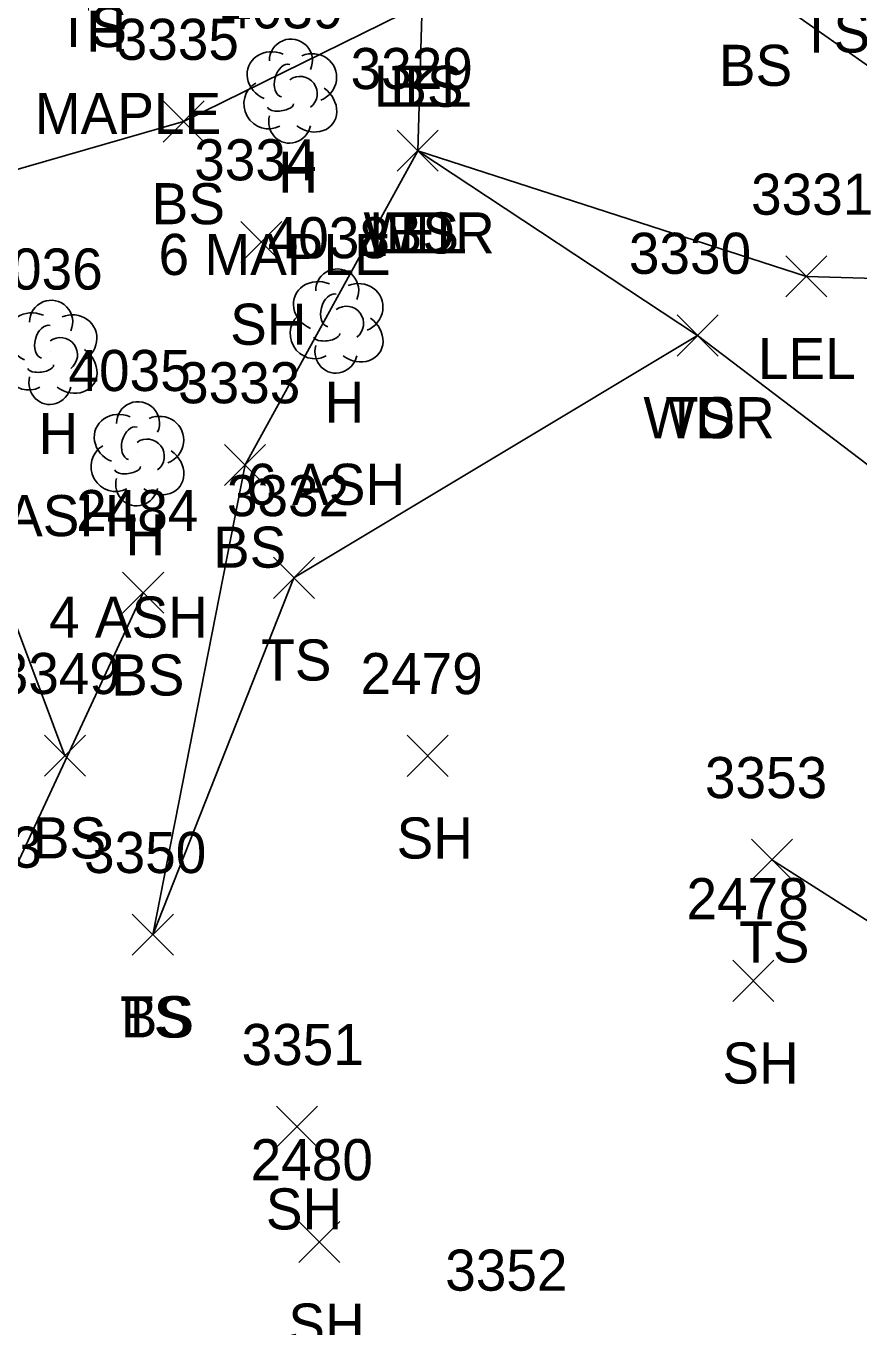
# Model space of a CAD drawing. Extents: x 1461855 to 1464118, y 556196 to 557441.
# Drawn here: x 1462017.7 to 1462058.2, y 556555.9 to 556619.2 of the extents above; entities that cross this region are included whole.
import ezdxf

# ---------------------------------------------------------------- set-up
doc = ezdxf.new("R2010")
doc.units = 0
for name, color, linetype in [('L_A', 7, 'Continuous'), ('L_C', 7, 'Continuous'), ('L_I', 7, 'Continuous'), ('L_TIC', 7, 'Continuous'), ('LARO', 7, 'Continuous'), ('LAWA', 7, 'Continuous'), ('LELB', 7, 'Continuous'), ('LTD', 7, 'Continuous')]:
    doc.layers.add(name, color=color, linetype=linetype)

msp = doc.modelspace()

# ---------------------------------------------------------------- linework, layer by layer
at = {"layer": 'L_TIC'}
for points in [[(1462024.387, 556613.515), (1462026.387, 556615.515)], [(1462026.387, 556613.515), (1462024.387, 556615.515)], [(1462035.776, 556612.093), (1462037.776, 556614.093)], [(1462037.776, 556612.093), (1462035.776, 556614.093)], [(1462035.776, 556612.093), (1462037.776, 556614.093)], [(1462037.776, 556612.093), (1462035.776, 556614.093)], [(1462035.776, 556612.093), (1462037.776, 556614.093)], [(1462037.776, 556612.093), (1462035.776, 556614.093)], [(1462028.161, 556607.651), (1462030.161, 556609.651)], [(1462030.161, 556607.651), (1462028.161, 556609.651)], [(1462054.688, 556605.979), (1462056.688, 556607.979)], [(1462056.688, 556605.979), (1462054.688, 556607.979)], [(1462049.396, 556603.102), (1462051.396, 556605.102)], [(1462051.396, 556603.102), (1462049.396, 556605.102)], [(1462049.396, 556603.102), (1462051.396, 556605.102)], [(1462051.396, 556603.102), (1462049.396, 556605.102)], [(1462027.375, 556596.803), (1462029.375, 556598.803)], [(1462029.375, 556596.803), (1462027.375, 556598.803)], [(1462029.751, 556591.31), (1462031.751, 556593.31)], [(1462031.751, 556591.31), (1462029.751, 556593.31)], [(1462022.416, 556590.583), (1462024.416, 556592.583)], [(1462024.416, 556590.583), (1462022.416, 556592.583)], [(1462018.608, 556582.655), (1462020.608, 556584.655)], [(1462020.608, 556582.655), (1462018.608, 556584.655)], [(1462036.259, 556582.649), (1462038.259, 556584.649)], [(1462038.259, 556582.649), (1462036.259, 556584.649)], [(1462053.01, 556577.59), (1462055.01, 556579.59)], [(1462055.01, 556577.59), (1462053.01, 556579.59)], [(1462022.886, 556573.944), (1462024.886, 556575.944)], [(1462024.886, 556573.944), (1462022.886, 556575.944)], [(1462022.886, 556573.944), (1462024.886, 556575.944)], [(1462024.886, 556573.944), (1462022.886, 556575.944)], [(1462052.11, 556571.698), (1462054.11, 556573.698)], [(1462054.11, 556571.698), (1462052.11, 556573.698)], [(1462029.898, 556564.6), (1462031.898, 556566.6)], [(1462031.898, 556564.6), (1462029.898, 556566.6)], [(1462030.993, 556558.995), (1462032.993, 556560.995)], [(1462032.993, 556558.995), (1462030.993, 556560.995)]]:
    msp.add_lwpolyline(points, dxfattribs=at)
at = {"layer": 'LARO'}
msp.add_lwpolyline([(1462028.293, 556804.845), (1462029.856, 556786.264), (1462034.967, 556768.458), (1462036.472, 556762.979), (1462033.427, 556748.898), (1462029.252, 556744.558), (1462032.364, 556727.057), (1462032.403, 556719.386), (1462031.75, 556687.131), (1462035.594, 556661.411), (1462033.996, 556641.147), (1462031.483, 556628.768), (1462037, 556620.231), (1462036.776, 556613.093), (1462055.688, 556606.979), (1462067.548, 556606.631), (1462078.525, 556595.396), (1462093.66, 556580.158), (1462100.331, 556564.645), (1462103.465, 556550.963), (1462104.582, 556534.352), (1462113.504, 556526.22)], dxfattribs=at)
at = {"layer": 'LAWA'}
msp.add_lwpolyline([(1462036.776, 556613.093), (1462050.396, 556604.102), (1462080.299, 556581.377), (1462088.118, 556572.25), (1462090.708, 556561.628), (1462095.286, 556550.274), (1462094.272, 556539.371)], dxfattribs=at)
at = {"layer": 'LELB'}
for points in [[(1462033.427, 556748.898), (1462037.255, 556728.002), (1462037.528, 556719.234), (1462036.024, 556686.385), (1462043.522, 556661.49), (1462038.833, 556639.233), (1462052.988, 556621.249), (1462067.983, 556610.68)], [(1462037, 556620.231), (1462025.387, 556614.515), (1462007.069, 556609.236), (1462003.91, 556604.783)], [(1462036.776, 556613.093), (1462028.375, 556597.803), (1462023.886, 556574.944)], [(1462007.069, 556609.236), (1462009.837, 556605.016), (1462011.898, 556601.66), (1462015.028, 556595.847), (1462019.608, 556583.655)], [(1462050.396, 556604.102), (1462030.751, 556592.31), (1462023.886, 556574.944)], [(1462073.826, 556488.172), (1462058.724, 556498.395), (1462047.72, 556513.704), (1462037.062, 556530.069), (1462022.313, 556535.546), (1462008.95, 556552.393), (1462011.129, 556562.18), (1462015.8, 556575.203), (1462023.416, 556591.583)], [(1462054.01, 556578.59), (1462066.074, 556570.901), (1462081.079, 556559.746), (1462094.272, 556539.371)]]:
    msp.add_lwpolyline(points, dxfattribs=at)
at = {"layer": 'LTD'}
for p, q in [((1462030.559, 556616.047), (1462030.559, 556616.047)), ((1462030.559, 556616.047), (1462030.559, 556616.047)), ((1462032.812, 556604.861), (1462032.812, 556604.861)), ((1462032.812, 556604.861), (1462032.812, 556604.861)), ((1462018.894, 556603.336), (1462018.894, 556603.336)), ((1462018.894, 556603.336), (1462018.894, 556603.336)), ((1462023.119, 556598.399), (1462023.119, 556598.399)), ((1462023.119, 556598.399), (1462023.119, 556598.399))]:
    msp.add_line(p, q, dxfattribs=at)
for centre in [(1462030.606, 556617.481), (1462032.859, 556606.295), (1462018.941, 556604.77), (1462023.166, 556599.833)]:
    msp.add_arc(centre, 1.047, 335.52715, 180.95627, dxfattribs=at)
for centre, major_axis, ratio, start_param, end_param in [((1462029.767, 556616.713), (1.21, -0.512), 0.895232, 1.570796, 4.712389), ((1462031.6, 556616.63), (-1.141, -0.483), 0.949671, 1.570796, 4.712389), ((1462030.35, 556616.505), (-0.208, -0.792), 0.645439, 3.141593, 6.283185), ((1462031.059, 556615.88), (-0.5, 0.667), 0.989748, 3.141593, 6.283185), ((1462029.476, 556615.338), (0.584, -1.042), 0.959034, 3.141593, 6.283185), ((1462031.559, 556615.214), (-1.09, 0.792), 0.841452, 1.570796, 4.712389), ((1462030.101, 556615.297), (-0.625, -0.083), 0.423636, 0, 3.141593), ((1462030.559, 556614.547), (0.265, 1.061), 0.942809, 1.570796, 4.712389), ((1462032.02, 556605.527), (1.21, -0.512), 0.895232, 1.570796, 4.712389), ((1462033.854, 556605.444), (-1.141, -0.483), 0.949671, 1.570796, 4.712389), ((1462032.604, 556605.319), (-0.208, -0.792), 0.645439, 3.141593, 6.283185), ((1462033.312, 556604.694), (-0.5, 0.667), 0.989748, 3.141593, 6.283185), ((1462018.102, 556604.003), (1.21, -0.512), 0.895232, 1.570796, 4.712389), ((1462019.936, 556603.92), (-1.141, -0.483), 0.949671, 1.570796, 4.712389), ((1462031.729, 556604.152), (0.584, -1.042), 0.959034, 3.141593, 6.283185), ((1462033.812, 556604.028), (-1.09, 0.792), 0.841452, 1.570796, 4.712389), ((1462018.686, 556603.795), (-0.208, -0.792), 0.645439, 3.141593, 6.283185), ((1462032.354, 556604.111), (-0.625, -0.083), 0.423636, 0, 3.141593), ((1462017.811, 556602.628), (0.584, -1.042), 0.959034, 3.141593, 6.283185), ((1462019.394, 556603.17), (-0.5, 0.667), 0.989748, 3.141593, 6.283185), ((1462032.812, 556603.361), (0.265, 1.061), 0.942809, 1.570796, 4.712389), ((1462019.894, 556602.503), (-1.09, 0.792), 0.841452, 1.570796, 4.712389), ((1462018.436, 556602.586), (-0.625, -0.083), 0.423636, 0, 3.141593), ((1462018.894, 556601.836), (0.265, 1.061), 0.942809, 1.570796, 4.712389), ((1462022.328, 556599.065), (1.21, -0.512), 0.895232, 1.570796, 4.712389), ((1462024.161, 556598.982), (-1.141, -0.483), 0.949671, 1.570796, 4.712389), ((1462022.911, 556598.857), (-0.208, -0.792), 0.645439, 3.141593, 6.283185), ((1462023.619, 556598.232), (-0.5, 0.667), 0.989748, 3.141593, 6.283185), ((1462022.036, 556597.69), (0.584, -1.042), 0.959034, 3.141593, 6.283185), ((1462024.12, 556597.565), (-1.09, 0.792), 0.841452, 1.570796, 4.712389), ((1462022.661, 556597.649), (-0.625, -0.083), 0.423636, 0, 3.141593), ((1462023.12, 556596.899), (0.265, 1.061), 0.942809, 1.570796, 4.712389)]:
    msp.add_ellipse(centre, major_axis=major_axis, ratio=ratio, start_param=start_param, end_param=end_param, dxfattribs=at)

# ---------------------------------------------------------------- texts
at = {"layer": 'L_A'}
for s, p in [('TS', (1462019.213, 556618.137)), ('H', (1462020.65, 556617.908)), ('TS', (1462055.366, 556617.87)), ('BS', (1462051.429, 556616.249)), ('LEL', (1462034.637, 556615.231)), ('BS', (1462035.441, 556615.231)), ('H', (1462029.992, 556611.047)), ('BS', (1462023.828, 556609.515)), ('WDR', (1462034.138, 556608.093)), ('LEL', (1462034.414, 556608.093)), ('BS', (1462035.217, 556608.093)), ('SH', (1462027.649, 556603.651)), ('LEL', (1462053.326, 556601.979)), ('H', (1462032.245, 556599.861)), ('WDR', (1462047.758, 556599.102)), ('TS', (1462048.805, 556599.102)), ('H', (1462018.327, 556598.336)), ('H', (1462022.552, 556593.399)), ('BS', (1462026.815, 556592.803)), ('TS', (1462029.161, 556587.31)), ('BS', (1462021.857, 556586.583)), ('BS', (1462018.049, 556578.655)), ('SH', (1462035.747, 556578.649)), ('TS', (1462052.419, 556573.59)), ('TS', (1462022.296, 556569.944)), ('BS', (1462022.327, 556569.944)), ('SH', (1462051.599, 556567.698)), ('SH', (1462029.386, 556560.6)), ('SH', (1462030.481, 556554.995))]:
    msp.add_text(s, height=2, dxfattribs=at).set_placement(p)
at = {"layer": 'L_C'}
for s, p in [('10 MAPLE', (1462014.429, 556613.908)), ('6 MAPLE', (1462024.165, 556607.047)), ('6 ASH', (1462028.434, 556595.861)), ('6 ASH', (1462014.516, 556594.336)), ('4 ASH', (1462018.836, 556589.399))]:
    msp.add_text(s, height=2, dxfattribs=at).set_placement(p)
at = {"layer": 'L_I'}
for s, p in [('4039', (1462027.212, 556619.047)), ('3335', (1462022.127, 556617.515)), ('3329', (1462033.509, 556616.093)), ('3329', (1462033.509, 556616.093)), ('3329', (1462033.509, 556616.093)), ('3334', (1462025.901, 556611.651)), ('3331', (1462052.995, 556609.979)), ('4038', (1462029.474, 556607.861)), ('3330', (1462047.049, 556607.102)), ('3330', (1462047.049, 556607.102)), ('4036', (1462015.501, 556606.336)), ('4035', (1462019.781, 556601.399)), ('3333', (1462025.115, 556600.803)), ('3332', (1462027.491, 556595.31)), ('2484', (1462020.156, 556594.583)), ('3349', (1462016.34, 556586.655)), ('2479', (1462033.991, 556586.649)), ('3353', (1462050.75, 556581.59)), ('2483', (1462012.54, 556578.203)), ('3350', (1462020.54, 556577.944)), ('3350', (1462020.54, 556577.944)), ('2478', (1462049.851, 556575.698)), ('3351', (1462028.205, 556568.6)), ('2480', (1462028.646, 556562.995)), ('3352', (1462038.113, 556557.62))]:
    msp.add_text(s, height=2, dxfattribs=at).set_placement(p)

doc.saveas('drawing.dxf')
